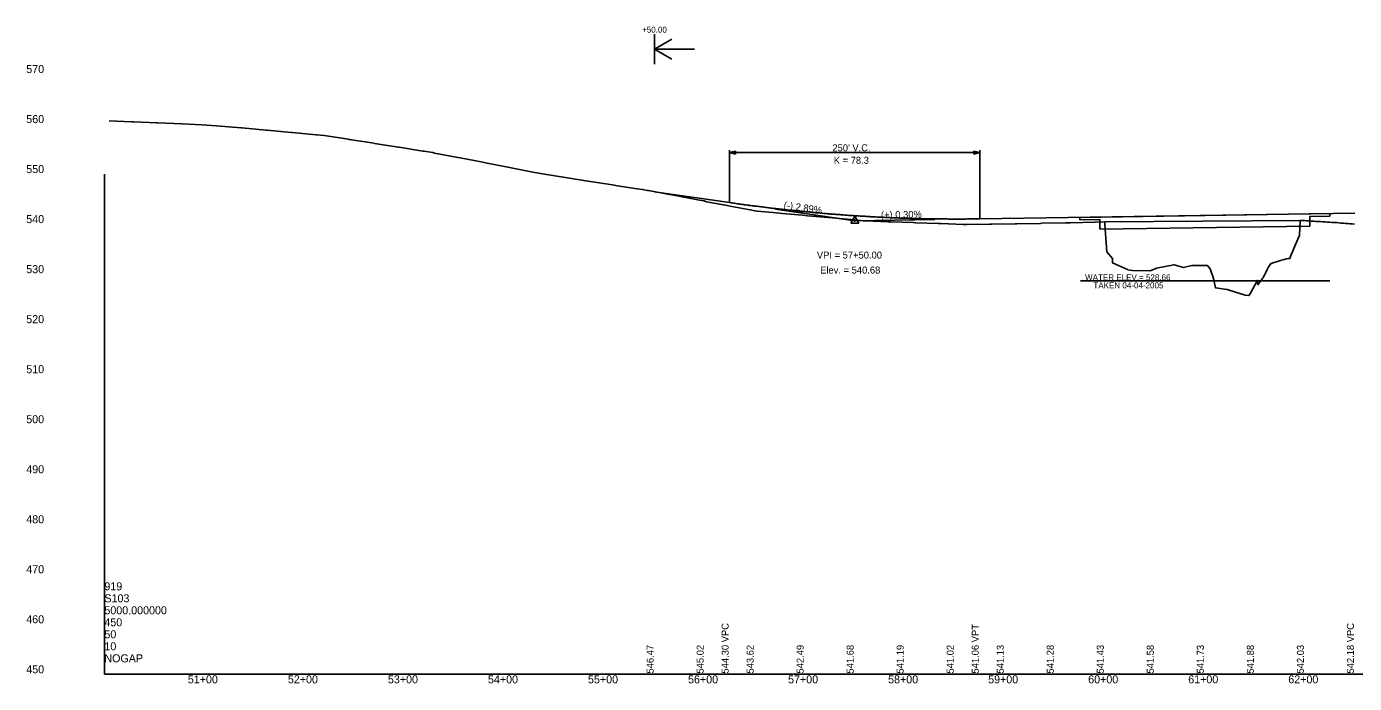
# Model space of a CAD drawing. Extents: x 49922 to 52613, y 49991 to 60509.
# Drawn here: x 49922 to 51250, y 49991 to 50647 of the extents above; entities that cross this region are included whole.
import ezdxf

# ---------------------------------------------------------------- set-up
doc = ezdxf.new("R2010")
doc.units = 0
for name, color, linetype in [('RD_DDB_ElevTX', 7, 'Continuous'), ('RD_DDB_GradeTX', 7, 'Continuous'), ('RD_DDB_Profile_EX', 7, 'Continuous'), ('RD_DDB_Profile_Lbl', 7, 'Continuous'), ('RD_DDB_Profile_PR', 7, 'Continuous'), ('RD_DDB_StaTX', 7, 'Continuous'), ('RD_DDB_StripGrade', 7, 'Continuous'), ('RD_DDB_VCLbl', 7, 'Continuous'), ('RD_GPK_Profile_Cell', 7, 'Continuous'), ('RD_Sketch2', 7, 'Continuous'), ('RD_Sketch8', 7, 'Continuous'), ('RD_TX_Profile', 7, 'Continuous')]:
    doc.layers.add(name, color=color, linetype=linetype)

msp = doc.modelspace()

# ---------------------------------------------------------------- linework, layer by layer
at = {"layer": 'RD_DDB_GradeTX'}
for p, q in [((50631, 50523), (50625, 50521.5)), ((50625, 50521.5), (50631, 50520)), ((50631, 50520), (50631, 50523)), ((50875, 50521.5), (50869, 50523)), ((50869, 50523), (50869, 50520)), ((50869, 50520), (50875, 50521.5)), ((50670.8, 50464.9), (50750, 50453.4)), ((50746, 50451.1), (50750, 50458)), ((50750, 50458), (50754, 50451.1)), ((50830, 50454.6), (50750, 50453.4)), ((50746, 50451.1), (50754, 50451.1))]:
    msp.add_line(p, q, dxfattribs=at)
msp.add_circle((50750, 50453.4), 0.529, dxfattribs=at)
at = {"layer": 'RD_DDB_Profile_EX'}
msp.add_line((51000, 50452.2), (51195.2, 50453.8), dxfattribs=at)
for points in [[(50004.7, 50553.4), (50027.3, 50552.4), (50029.1, 50552.3), (50052.3, 50551.3), (50053.5, 50551.2), (50077.3, 50550.1), (50077.9, 50550.1), (50097.5, 50549.2), (50102.4, 50548.9), (50111.8, 50548.4), (50112.2, 50548.4), (50136.8, 50546.1), (50137.4, 50546.1), (50161.8, 50543.8), (50162.6, 50543.8), (50186.8, 50541.6), (50187.8, 50541.5), (50211.8, 50539.3), (50212.2, 50539.2), (50219.7, 50538.5), (50244, 50534.8), (50244.7, 50534.6), (50269.7, 50530.8), (50270, 50530.7), (50294, 50526.9), (50294.7, 50526.8), (50318.3, 50523.1), (50319.7, 50522.8), (50327.9, 50521.5), (50328.4, 50521.5), (50330.1, 50521.1), (50353.4, 50516.6), (50355.6, 50516.2), (50378.4, 50511.8), (50381.1, 50511.3), (50403.4, 50507), (50406.5, 50506.3), (50428.3, 50502.1), (50436.1, 50500.6), (50437.8, 50500.3), (50458.6, 50497), (50462.8, 50496.3), (50483.3, 50493.1), (50487.8, 50492.4), (50507.9, 50489.2), (50512.8, 50488.4), (50532.6, 50485.3), (50537.8, 50484.5), (50542.7, 50483.7), (50543.8, 50483.5), (50563.1, 50479.8), (50568.8, 50478.9), (50570.5, 50478.6), (50589.8, 50474.9), (50594.8, 50474), (50599.4, 50473.2), (50602, 50472.4), (50620.7, 50468.8), (50627.1, 50467.7), (50645.5, 50464.2), (50650.2, 50463.4), (50652.7, 50462.9), (50671.7, 50461.2), (50677.7, 50460.6), (50697.7, 50458.9), (50702.7, 50458.4), (50723.7, 50456.5), (50727.6, 50456.2), (50749.8, 50454.2), (50752.6, 50453.9), (50753, 50453.9), (50758.6, 50453.4), (50761, 50453.3), (50783.6, 50452.4), (50786, 50452.4), (50808.6, 50451.5), (50811.1, 50451.4), (50833.6, 50450.5), (50836.1, 50450.5), (50858.6, 50449.6), (50859.1, 50449.6), (50862.2, 50449.5), (50885.1, 50449.9), (50887.2, 50449.9), (50910.5, 50450.4), (50912.2, 50450.4), (50935.8, 50450.8), (50937.2, 50450.9), (50961.2, 50451.3), (50962.2, 50451.3), (50964.8, 50451.4), (50965.7, 50451.4), (50990, 50451.9), (51000, 50452.2), (51000.1, 50449.8), (51002.1, 50422.3), (51007.6, 50415.5), (51007.8, 50411.2), (51022.6, 50404.5), (51023.1, 50404.2), (51027.7, 50403.5)], [(51027.7, 50403.5), (51045.5, 50403.2), (51051.8, 50406), (51068.9, 50409.4), (51069.3, 50409.4), (51078.6, 50406.6), (51087.1, 50408.6), (51090, 50408.7), (51101.6, 50408.8), (51102.2, 50408.9), (51105.4, 50405.3), (51108.5, 50395.5), (51110.7, 50386.2), (51121.9, 50384.7), (51122.7, 50384.6), (51124.3, 50384.1), (51140.4, 50379), (51144.1, 50378.6), (51145.6, 50380.9), (51152.5, 50393.9), (51153.1, 50389.4), (51157.4, 50395.2), (51158.3, 50396.2), (51162.3, 50404.8), (51163.4, 50406.6), (51166, 50410.6), (51166.7, 50410.8), (51168, 50411.2), (51170.2, 50411.9), (51172.5, 50412.6), (51174.8, 50413.3), (51177, 50414), (51179.3, 50414.7), (51181.6, 50415.3), (51183.9, 50415.7), (51184.9, 50415.8), (51186.1, 50418.7), (51188.4, 50424.1), (51190.7, 50429.5), (51192.9, 50434.9), (51194.5, 50438.7), (51195.2, 50453.8), (51197.5, 50453.6), (51199.7, 50453.5), (51202, 50453.4), (51204.3, 50453.2), (51206.6, 50453.1), (51208.8, 50453), (51211.1, 50452.8), (51213.4, 50452.7), (51215.6, 50452.6), (51217.9, 50452.4), (51219.3, 50452.3), (51220.2, 50452.3), (51222.4, 50452.1), (51224.7, 50451.9), (51227, 50451.8), (51229.3, 50451.6), (51231.5, 50451.5), (51233.8, 50451.3), (51236.1, 50451.1), (51238.3, 50451), (51238.6, 50450.9), (51240.6, 50450.7), (51242.9, 50450.6), (51245.1, 50450.4), (51247.4, 50450.2), (51249.7, 50450.1)]]:
    msp.add_lwpolyline(points, dxfattribs=at)
at = {"layer": 'RD_DDB_Profile_PR'}
for p, q in [((50550, 50482.4), (50625, 50471.5)), ((50875, 50455.3), (51250, 50460.9))]:
    msp.add_line(p, q, dxfattribs=at)
msp.add_spline([(50625, 50471.5), (50630, 50470.8), (50635, 50470.1), (50640, 50469.4), (50645, 50468.7), (50650, 50468.1), (50655, 50467.5), (50660, 50466.8), (50665, 50466.2), (50670, 50465.6), (50675, 50465.1), (50680, 50464.5), (50685, 50464), (50690, 50463.5), (50695, 50462.9), (50700, 50462.5), (50705, 50462), (50710, 50461.5), (50715, 50461.1), (50720, 50460.6), (50725, 50460.2), (50730, 50459.8), (50735, 50459.5), (50740, 50459.1), (50745, 50458.7), (50750, 50458.4), (50755, 50458.1), (50760, 50457.8), (50765, 50457.5), (50770, 50457.2), (50775, 50457), (50780, 50456.8), (50785, 50456.5), (50790, 50456.3), (50795, 50456.1), (50800, 50456), (50805, 50455.8), (50810, 50455.7), (50815, 50455.5), (50820, 50455.4), (50825, 50455.3), (50830, 50455.3), (50835, 50455.2), (50840, 50455.2), (50845, 50455.1), (50850, 50455.1), (50855, 50455.1), (50860, 50455.1), (50865, 50455.2), (50870, 50455.2), (50875, 50455.3)], degree=3, dxfattribs=at)
at = {"layer": 'RD_DDB_VCLbl'}
for p, q in [((50625, 50524), (50625, 50471.5)), ((50625, 50521.5), (50875, 50521.5)), ((50875, 50524), (50875, 50455.3))]:
    msp.add_line(p, q, dxfattribs=at)
at = {"layer": 'RD_GPK_Profile_Cell'}
for q in [(50000, 50500), (52600, 50000), (50000, 50000)]:
    msp.add_line((50000, 50000), q, dxfattribs=at)
at = {"layer": 'RD_Sketch2'}
msp.add_line((50975.8, 50393.3), (51225.1, 50393.3), dxfattribs=at)
at = {"layer": 'RD_Sketch8'}
for p, q in [((50975.1, 50456.8), (51225.1, 50460.6)), ((50975.1, 50454.3), (50975.1, 50456.8)), ((50975.1, 50454.3), (50995.1, 50454.6)), ((50995.1, 50445), (50995.1, 50454.6)), ((51205.1, 50457.7), (51225.1, 50458)), ((51205.1, 50448.1), (51205.1, 50457.7)), ((51225.1, 50458), (51225.1, 50460.6)), ((50995.1, 50445), (51205.1, 50448.1))]:
    msp.add_line(p, q, dxfattribs=at)
msp.add_lwpolyline([(50975.1, 50454.3), (50975.1, 50456.8), (50975.8, 50456.8), (51225.1, 50460.6), (51225.1, 50458), (51205.1, 50457.7), (51205.1, 50448.1), (50995.1, 50445), (50995.1, 50454.6)], close=True, dxfattribs=at)
at = {"layer": 'RD_TX_Profile'}
for p, q in [((50550, 50640), (50550, 50610)), ((50550, 50625), (50567.3, 50635)), ((50550, 50625), (50567.3, 50615)), ((50550, 50625), (50590, 50625))]:
    msp.add_line(p, q, dxfattribs=at)

# ---------------------------------------------------------------- texts
at = {"layer": 'RD_DDB_ElevTX'}
for s, p in [('570', (49921.9, 50601)), ('560', (49921.9, 50551)), ('550', (49921.9, 50501)), ('540', (49921.9, 50451)), ('530', (49921.9, 50401)), ('520', (49921.9, 50351)), ('510', (49921.9, 50301)), ('500', (49921.9, 50251)), ('490', (49921.9, 50201)), ('480', (49921.9, 50151)), ('470', (49921.9, 50101)), ('460', (49921.9, 50051)), ('450', (49921.9, 50001))]:
    msp.add_text(s, height=8, dxfattribs=at).set_placement(p)
at = {"layer": 'RD_DDB_GradeTX'}
for s, rotation, p in [('(-) 2.89%', 351.7701, (50678.7, 50465.8)), ('(+) 0.30%', 0.8594, (50776.3, 50455.8))]:
    msp.add_text(s, height=7, rotation=rotation, dxfattribs=at).set_placement(p)
at = {"layer": 'RD_DDB_Profile_Lbl'}
for s, p in [('VPI = 57+50.00', (50712.2, 50415.6)), ('Elev. = 540.68', (50715.5, 50400.6))]:
    msp.add_text(s, height=7, dxfattribs=at).set_placement(p)
at = {"layer": 'RD_DDB_StaTX'}
for s, p in [('51+00', (50083.4, 49991)), ('52+00', (50183.4, 49991)), ('53+00', (50283.4, 49991)), ('54+00', (50383.4, 49991)), ('55+00', (50483.4, 49991)), ('56+00', (50583.4, 49991)), ('57+00', (50683.4, 49991)), ('58+00', (50783.4, 49991)), ('59+00', (50883.4, 49991)), ('60+00', (50983.4, 49991)), ('61+00', (51083.4, 49991)), ('62+00', (51183.4, 49991))]:
    msp.add_text(s, height=8, dxfattribs=at).set_placement(p)
at = {"layer": 'RD_DDB_StripGrade'}
for s, p in [('544.30 VPC', (50624, 50000.8)), ('541.06 VPT', (50874, 50000.8)), ('542.18 VPC', (51249, 50000.8)), ('546.47', (50549, 50000.8)), ('545.02', (50599, 50000.8)), ('543.62', (50649, 50000.8)), ('542.49', (50699, 50000.8)), ('541.68', (50749, 50000.8)), ('541.19', (50799, 50000.8)), ('541.02', (50849, 50000.8)), ('541.13', (50899, 50000.8)), ('541.28', (50949, 50000.8)), ('541.43', (50999, 50000.8)), ('541.58', (51049, 50000.8)), ('541.73', (51099, 50000.8)), ('541.88', (51149, 50000.8)), ('542.03', (51199, 50000.8)), ('542.18', (51249, 50000.8))]:
    msp.add_text(s, height=7, rotation=90, dxfattribs=at).set_placement(p)
at = {"layer": 'RD_DDB_VCLbl'}
for s, p in [("250' V.C.", (50727.7, 50522.8)), ('K = 78.3', (50729.1, 50510.3))]:
    msp.add_text(s, height=7, dxfattribs=at).set_placement(p)
at = {"layer": 'RD_GPK_Profile_Cell'}
for s, p in [('919', (50000, 50084)), ('5000.000000', (50000, 50060)), ('S103', (50000, 50072)), ('450', (50000, 50048)), ('50', (50000, 50036)), ('10', (50000, 50024)), ('NOGAP', (50000, 50012))]:
    msp.add_text(s, height=8, dxfattribs=at).set_placement(p)
at = {"layer": 'RD_TX_Profile'}
for s, p in [('+50.00', (50537.5, 50641.4)), ('WATER ELEV.= 528.66', (50980.3, 50393.8)), ('TAKEN 04-04-2005', (50988.6, 50385.8))]:
    msp.add_text(s, height=6, dxfattribs=at).set_placement(p)

doc.saveas('drawing.dxf')
